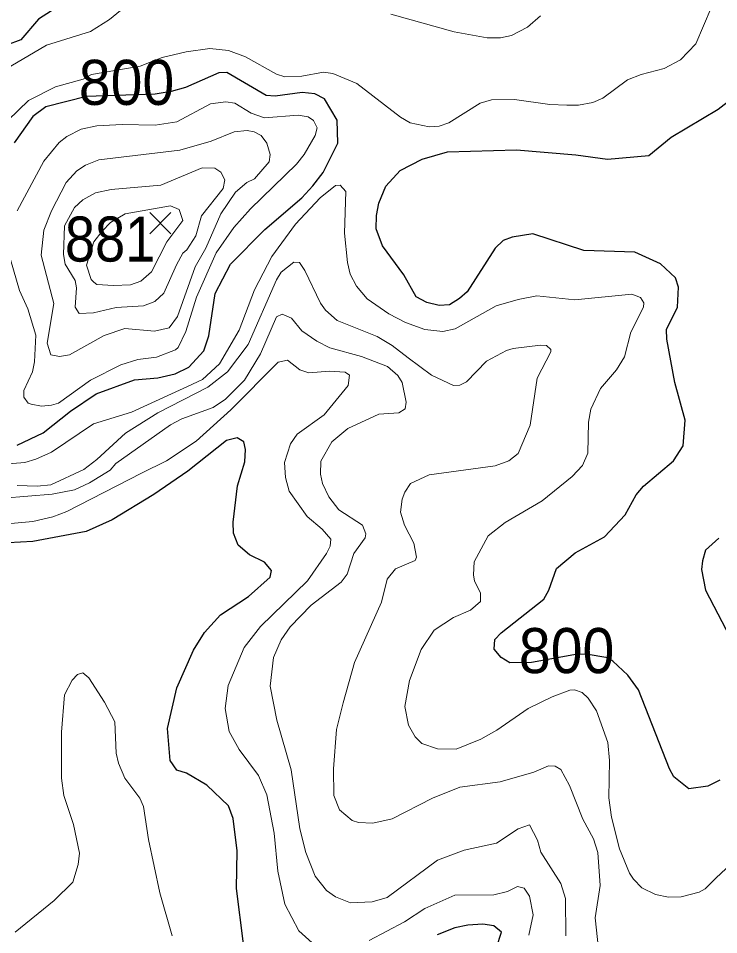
# Model space of a CAD drawing. Extents: x 294.2 to 320.3, y 7482.7 to 7510.7.
# Drawn here: x 312.401 to 313.645, y 7489.244 to 7490.87 of the extents above; entities that cross this region are included whole.
import ezdxf
from ezdxf.enums import TextEntityAlignment as Align

# ---------------------------------------------------------------- set-up
doc = ezdxf.new("R2010")
doc.units = 0
doc.header["$LTSCALE"] = 0.032
for name, color, linetype, lineweight in [('1', 7, 'Continuous', 25), ('2', 7, 'Continuous', 13), ('21', 7, 'Continuous', 25)]:
    doc.layers.add(name, color=color, linetype=linetype, lineweight=lineweight)
doc.layers.add('61', color=7, linetype='Continuous')

msp = doc.modelspace()

# ---------------------------------------------------------------- linework, layer by layer
at = {"layer": '1'}
for points in [[(312.942, 7490.9409), (312.9265, 7490.9269), (312.9165, 7490.9226), (312.8971, 7490.9269), (312.8622, 7490.9576), (312.8461, 7490.9645), (312.7994, 7490.9791), (312.7434, 7490.9904), (312.724, 7491.0038), (312.6774, 7491.056), (312.6652, 7491.0598), (312.6563, 7491.0565), (312.6463, 7491.0506), (312.6208, 7491.0156), (312.5992, 7490.964), (312.5693, 7490.9215), (312.5576, 7490.9113), (312.5232, 7490.8962), (312.5016, 7490.8898), (312.4595, 7490.8839), (312.4367, 7490.8688), (312.4051, 7490.8322), (312.3535, 7490.8134)], [(312.3988, 7490.1129), (312.445, 7490.1346), (312.4934, 7490.1734), (312.5392, 7490.2037), (312.6073, 7490.2285), (312.6484, 7490.2324), (312.6794, 7490.2394), (312.7035, 7490.251), (312.7306, 7490.28), (312.7395, 7490.3068), (312.7503, 7490.3822), (312.7779, 7490.4338), (312.8387, 7490.4959), (312.9046, 7490.5517), (312.924, 7490.5734), (312.9425, 7490.5967), (312.9681, 7490.6487), (312.9673, 7490.6898), (312.9444, 7490.7278), (312.9274, 7490.7363), (312.9049, 7490.7386), (312.8568, 7490.7324), (312.8413, 7490.7332), (312.771, 7490.7743), (312.757, 7490.7735), (312.6979, 7490.7479), (312.6724, 7490.7405), (312.6437, 7490.7358), (312.5222, 7490.7319), (312.4499, 7490.7132), (312.4266, 7490.6962), (312.3935, 7490.6497)], [(313.6468, 7489.5183), (313.6257, 7489.5074), (313.5918, 7489.5029), (313.565, 7489.524), (313.5574, 7489.5381), (313.5025, 7489.6785), (313.4833, 7489.7047), (313.4567, 7489.7295), (313.4477, 7489.7354), (313.4095, 7489.7418), (313.3878, 7489.7407), (313.3124, 7489.7273), (313.2741, 7489.7263), (313.2586, 7489.736), (313.2458, 7489.7505), (313.2475, 7489.7677), (313.2586, 7489.78), (313.334, 7489.8392), (313.3429, 7489.8553), (313.3568, 7489.8941), (313.39, 7489.9215), (313.4422, 7489.95), (313.4788, 7489.9889), (313.498, 7490.0246), (313.5114, 7490.0399), (313.5648, 7490.085), (313.582, 7490.1114), (313.5854, 7490.1571), (313.567, 7490.2243), (313.5526, 7490.3007), (313.5521, 7490.3184), (313.5715, 7490.3577), (313.5737, 7490.3932), (313.5682, 7490.4099), (313.5415, 7490.4346), (313.4961, 7490.4551), (313.4051, 7490.4583), (313.3147, 7490.4879), (313.2781, 7490.482), (313.262, 7490.4761), (313.2476, 7490.4626), (313.1983, 7490.3847), (313.1844, 7490.3734), (313.1667, 7490.3621), (313.1484, 7490.3605), (313.1262, 7490.3659), (313.1073, 7490.3761), (313.0857, 7490.4154), (313.0475, 7490.4664), (313.0364, 7490.4966), (313.0369, 7490.5202), (313.0414, 7490.5423), (313.0536, 7490.5724), (313.0791, 7490.6004), (313.1179, 7490.6203), (313.1634, 7490.6337), (313.2855, 7490.637), (313.3914, 7490.6284), (313.4474, 7490.6203), (313.5206, 7490.6268), (313.5605, 7490.6596), (313.6437, 7490.7091), (313.6914, 7490.7457)], [(312.8008, 7489.2278), (312.7881, 7489.3261), (312.7893, 7489.3925), (312.7823, 7489.45), (312.774, 7489.4729), (312.7357, 7489.5093), (312.6994, 7489.5304), (312.6821, 7489.5359), (312.6703, 7489.5532), (312.666, 7489.6098), (312.6825, 7489.6822), (312.7118, 7489.749), (312.7315, 7489.7804), (312.7598, 7489.8119), (312.8097, 7489.8441), (312.8483, 7489.8787), (312.8506, 7489.8905), (312.838, 7489.9054), (312.8113, 7489.918), (312.7916, 7489.9353), (312.783, 7489.9565), (312.7826, 7489.9762), (312.7904, 7490.0407), (312.803, 7490.0832), (312.8046, 7490.1052), (312.8015, 7490.1185), (312.7897, 7490.1256), (312.7704, 7490.1209), (312.702, 7490.0667), (312.6417, 7490.025), (312.5677, 7489.9801), (312.5216, 7489.9597), (312.4266, 7489.9416), (312.3383, 7489.9374)], [(313.6454, 7489.9476), (313.6216, 7489.9267), (313.6161, 7489.9073), (313.6144, 7489.8923), (313.6216, 7489.8557), (313.6723, 7489.7577)], [(313.2501, 7489.2212), (313.2588, 7489.2487), (313.2454, 7489.2598), (313.226, 7489.2629), (313.1992, 7489.261), (313.1762, 7489.2559), (313.1449, 7489.2437)]]:
    msp.add_lwpolyline(points, dxfattribs=at)
at = {"layer": '2'}
for points in [[(312.612, 7490.9089), (312.5626, 7490.8682), (312.5293, 7490.8471), (312.4507, 7490.8228), (312.3877, 7490.7857)], [(312.3826, 7490.6899), (312.4189, 7490.7245), (312.4666, 7490.749), (312.5159, 7490.7626), (312.5308, 7490.771), (312.6175, 7490.7857), (312.6565, 7490.801), (312.6987, 7490.8112), (312.7408, 7490.817), (312.774, 7490.8131), (312.8046, 7490.8023), (312.8596, 7490.7716), (312.8742, 7490.7665), (312.9046, 7490.7678), (312.9426, 7490.7748), (312.9592, 7490.7723), (313.0019, 7490.755), (313.0798, 7490.695), (313.0971, 7490.6848), (313.1303, 7490.6778), (313.1481, 7490.679), (313.1654, 7490.6848), (313.2209, 7490.7199), (313.2414, 7490.7256), (313.2822, 7490.7263), (313.3448, 7490.7174), (313.3754, 7490.7161), (313.3959, 7490.7161), (313.4214, 7490.7212), (313.4393, 7490.7288), (313.4827, 7490.7614), (313.507, 7490.771), (313.5478, 7490.7812), (313.5772, 7490.7965), (313.604, 7490.8253), (313.6315, 7490.8891)], [(313.3281, 7490.8751), (313.3052, 7490.8546), (313.2771, 7490.8399), (313.2573, 7490.8361), (313.2337, 7490.8361), (313.175, 7490.8463), (313.0626, 7490.8776)], [(312.387, 7490.4422), (312.403, 7490.3873), (312.4177, 7490.3547), (312.4317, 7490.3081), (312.4298, 7490.2608), (312.426, 7490.243), (312.4107, 7490.2098), (312.4107, 7490.1983), (312.4183, 7490.1874), (312.4235, 7490.1855), (312.442, 7490.1823), (312.4599, 7490.1836), (312.472, 7490.1874), (312.5288, 7490.2283), (312.5831, 7490.2557), (312.6131, 7490.2646), (312.6463, 7490.2691), (312.6801, 7490.2819), (312.6846, 7490.2864), (312.6986, 7490.3145), (312.7172, 7490.3758), (312.7522, 7490.4543), (312.7836, 7490.499), (312.8135, 7490.5322), (312.8947, 7490.6114), (312.9087, 7490.6286), (312.9278, 7490.6624), (312.9317, 7490.6759), (312.9253, 7490.6893), (312.9157, 7490.6956), (312.8979, 7490.6988), (312.8378, 7490.6937), (312.8142, 7490.702), (312.7855, 7490.7199), (312.7695, 7490.7225), (312.7421, 7490.7186), (312.6821, 7490.6866), (312.6437, 7490.6809), (312.585, 7490.6822), (312.5403, 7490.6796), (312.5122, 7490.6739), (312.4867, 7490.6605), (312.4732, 7490.6503), (312.4464, 7490.6171), (312.3985, 7490.529)], [(313.1231, 7490.3182), (313.0886, 7490.3305), (313.0587, 7490.3458), (313.0204, 7490.3725), (313.0013, 7490.3949), (312.9904, 7490.4166), (312.9853, 7490.4371), (312.9802, 7490.4894), (312.9828, 7490.5628), (312.9725, 7490.5743), (312.9643, 7490.5737), (312.9368, 7490.5519), (312.8932, 7490.505), (312.8513, 7490.4476), (312.8206, 7490.3885), (312.7931, 7490.317), (312.758, 7490.257), (312.728, 7490.2295), (312.7012, 7490.2168), (312.6016, 7490.1714), (312.5346, 7490.1504), (312.4599, 7490.1006), (312.4318, 7490.0878), (312.4126, 7490.082), (312.3756, 7490.0789)], [(312.3986, 7490.0412), (312.4343, 7490.0399), (312.4586, 7490.0424), (312.5173, 7490.0699), (312.5403, 7490.0872), (312.5914, 7490.1344), (312.6489, 7490.1702), (312.7376, 7490.2155), (312.7721, 7490.2429), (312.8091, 7490.2915), (312.8595, 7490.4064), (312.8678, 7490.4198), (312.8902, 7490.4377), (312.9004, 7490.437), (312.91, 7490.423), (312.9374, 7490.3649), (312.9464, 7490.3527), (312.9674, 7490.3343), (313.0383, 7490.3055), (313.0651, 7490.2896), (313.0932, 7490.2679), (313.1347, 7490.2372), (313.1737, 7490.2187), (313.1852, 7490.2193), (313.1967, 7490.2251), (313.2324, 7490.2621), (313.2682, 7490.2806), (313.2797, 7490.2845), (313.3282, 7490.2902), (313.339, 7490.2896), (313.3467, 7490.2826), (313.3467, 7490.2787), (313.3224, 7490.2315), (313.3097, 7490.1485), (313.2886, 7490.098)], [(313.6583, 7489.3612), (313.6397, 7489.344), (313.6206, 7489.3255), (313.6104, 7489.3197), (313.5785, 7489.3114), (313.5555, 7489.3108), (313.5325, 7489.3153), (313.5082, 7489.3274), (313.4936, 7489.3427), (313.4865, 7489.3529), (313.4686, 7489.3964), (313.4546, 7489.4525), (313.4495, 7489.487), (313.4507, 7489.5534), (313.4482, 7489.5853), (313.4277, 7489.6415), (313.4131, 7489.6639), (313.4023, 7489.6741), (313.3888, 7489.6785), (313.3805, 7489.6779), (313.3492, 7489.6664), (313.3065, 7489.6453), (313.2509, 7489.607), (313.2222, 7489.5911), (313.1788, 7489.5732), (313.1456, 7489.5738), (313.1174, 7489.5834), (313.106, 7489.5949), (313.0939, 7489.616), (313.0875, 7489.6492), (313.0958, 7489.6952), (313.1162, 7489.7501), (313.1392, 7489.7845), (313.1737, 7489.8069), (313.2043, 7489.8197), (313.2216, 7489.8356), (313.2216, 7489.8509), (313.2113, 7489.8714), (313.2094, 7489.8829), (313.2107, 7489.9059), (313.2356, 7489.9518), (313.2656, 7489.9754), (313.3313, 7490.0138), (313.3843, 7490.0572), (313.4029, 7490.0769), (313.4124, 7490.0987), (313.4137, 7490.1536), (313.4175, 7490.1766), (313.4348, 7490.2136), (313.4635, 7490.2468), (313.4775, 7490.2698), (313.489, 7490.3132), (313.5114, 7490.3579), (313.512, 7490.3655), (313.5057, 7490.3751), (313.4904, 7490.3808), (313.3895, 7490.3706)], [(313.3895, 7490.3706), (313.3218, 7490.3778), (313.2885, 7490.3714), (313.2494, 7490.3602), (313.1765, 7490.3193), (313.1547, 7490.3143), (313.1231, 7490.3182)], [(313.3735, 7489.2418), (313.3728, 7489.3082), (313.3646, 7489.3351), (313.3288, 7489.3906), (313.323, 7489.4117), (313.309, 7489.4391), (313.2886, 7489.4321), (313.2503, 7489.4065), (313.1928, 7489.3938), (313.1451, 7489.3763), (313.0562, 7489.3102), (313.0294, 7489.3025), (312.9911, 7489.3005), (312.9643, 7489.3114), (312.9483, 7489.3223), (312.9279, 7489.3478), (312.9113, 7489.39), (312.901, 7489.4321), (312.8857, 7489.5368), (312.8602, 7489.6249), (312.848, 7489.6849), (312.8538, 7489.736), (312.8678, 7489.7673), (312.8838, 7489.7903), (312.9208, 7489.8286), (312.9744, 7489.8694), (312.9847, 7489.8841), (312.9968, 7489.9205), (313.0172, 7489.9486), (313.0178, 7489.9557), (313.0121, 7489.971), (312.97, 7489.9978), (312.9521, 7490.0214), (312.9412, 7490.045), (312.9374, 7490.0616), (312.9381, 7490.0846), (312.9579, 7490.1185), (312.9859, 7490.1427), (313.0409, 7490.1676), (313.0766, 7490.1701), (313.0881, 7490.1772), (313.09, 7490.1893), (313.0824, 7490.2238), (313.0747, 7490.2366), (313.0568, 7490.2525), (313.0102, 7490.2704), (312.954, 7490.2857), (312.9311, 7490.2972), (312.9043, 7490.3155), (312.8859, 7490.3383), (312.8693, 7490.3455), (312.8595, 7490.3405), (312.8308, 7490.2749), (312.8027, 7490.2282), (312.7689, 7490.1944), (312.7472, 7490.1798), (312.691, 7490.1593), (312.6712, 7490.1491), (312.5741, 7490.0801), (312.5639, 7490.0686), (312.5275, 7490.0457), (312.5007, 7490.0335), (312.4611, 7490.0258), (312.3743, 7490.0189)], [(312.9285, 7489.2239), (312.8991, 7489.2508), (312.8742, 7489.298), (312.8615, 7489.3568), (312.8551, 7489.4244), (312.8423, 7489.4921), (312.8276, 7489.5266), (312.7931, 7489.5725), (312.7752, 7489.6045), (312.7682, 7489.6454), (312.7733, 7489.6862), (312.8021, 7489.7539), (312.8308, 7489.7909), (312.9144, 7489.872), (312.9483, 7489.9205), (312.9547, 7489.9333), (312.956, 7489.946), (312.9406, 7489.9639), (312.9138, 7489.9863), (312.8819, 7490.031), (312.8755, 7490.0553), (312.8736, 7490.0821), (312.8844, 7490.1153), (312.8959, 7490.1325), (312.9442, 7490.1668), (312.9867, 7490.2186), (312.9889, 7490.2372), (312.9815, 7490.2422), (312.9534, 7490.2439), (312.9166, 7490.2411), (312.9011, 7490.2467), (312.8788, 7490.2637), (312.8621, 7490.2603), (312.7784, 7490.1753), (312.7165, 7490.1197), (312.6642, 7490.0853), (312.6195, 7490.0629), (312.4867, 7489.9952), (312.4624, 7489.9857), (312.4267, 7489.9773), (312.3475, 7489.9703)], [(313.2886, 7490.098), (313.272, 7490.0853), (313.2477, 7490.0763), (313.1303, 7490.0603), (313.0977, 7490.045), (313.0875, 7490.0297), (313.0824, 7490.017)], [(313.0824, 7490.017), (313.0798, 7489.994), (313.0868, 7489.971), (313.1034, 7489.939), (313.1079, 7489.9141), (313.106, 7489.9084), (313.0709, 7489.8931), (313.0562, 7489.8752), (313.0459, 7489.8343), (312.9981, 7489.7271), (312.9777, 7489.6556), (312.9662, 7489.6083), (312.9604, 7489.5381), (312.9611, 7489.4908), (312.9713, 7489.4653), (312.9936, 7489.4468), (313.0051, 7489.443), (313.0307, 7489.4417), (313.0651, 7489.4493), (313.1366, 7489.4864), (313.1852, 7489.5055), (313.2567, 7489.5151), (313.3167, 7489.5323), (313.3428, 7489.5438), (313.3544, 7489.5432), (313.3646, 7489.5374), (313.3799, 7489.5087), (313.4035, 7489.4487), (313.4226, 7489.4142), (313.4303, 7489.39), (313.4341, 7489.3312), (313.4252, 7489.2738), (313.4329, 7489.2023)], [(312.4962, 7489.6958), (312.5058, 7489.706), (312.5154, 7489.7086), (312.5262, 7489.6996), (312.5537, 7489.6569), (312.5722, 7489.6217), (312.5747, 7489.5662), (312.5786, 7489.5483), (312.5901, 7489.5215), (312.6169, 7489.4864), (312.6233, 7489.4717), (312.6322, 7489.413), (312.652, 7489.3185), (312.6743, 7489.2418)], [(312.5096, 7489.3887), (312.4988, 7489.4398), (312.4815, 7489.4908), (312.4777, 7489.5215), (312.4777, 7489.6032), (312.4828, 7489.6696), (312.4962, 7489.6958)], [(312.3954, 7489.2482), (312.4643, 7489.3044), (312.4975, 7489.337), (312.5071, 7489.3683), (312.5096, 7489.3887)], [(313.3077, 7489.2431), (313.3154, 7489.2789), (313.309, 7489.3121), (313.2995, 7489.3267), (313.2873, 7489.3293), (313.2695, 7489.3204), (313.2452, 7489.3146), (313.1762, 7489.314), (313.1226, 7489.2903), (313.0868, 7489.2667), (313.0243, 7489.2335)]]:
    msp.add_lwpolyline(points, dxfattribs=at)
for points in [[(312.7433, 7490.6522), (312.6878, 7490.6362), (312.5441, 7490.619), (312.5199, 7490.6101), (312.5045, 7490.5999), (312.486, 7490.5788), (312.4598, 7490.529), (312.4464, 7490.4945), (312.4413, 7490.4498), (312.4636, 7490.3643), (312.4522, 7490.2941), (312.4585, 7490.273), (312.4739, 7490.2704), (312.4918, 7490.273), (312.5531, 7490.3075), (312.5901, 7490.3202), (312.6425, 7490.3151), (312.6686, 7490.3208), (312.6833, 7490.3413), (312.7152, 7490.4294), (312.7338, 7490.4626), (312.7606, 7490.5233), (312.7867, 7490.5616), (312.8065, 7490.5788), (312.8206, 7490.5858), (312.8461, 7490.6158), (312.848, 7490.6286), (312.8423, 7490.649), (312.8321, 7490.6624), (312.82, 7490.6688), (312.8072, 7490.6714), (312.7842, 7490.6688)], [(312.7605, 7490.5972), (312.7497, 7490.6043), (312.7274, 7490.605), (312.654, 7490.5743), (312.5659, 7490.5667), (312.5377, 7490.5609), (312.5154, 7490.5481), (312.5007, 7490.5347), (312.4827, 7490.5022), (312.481, 7490.4511), (312.4843, 7490.4339), (312.5015, 7490.4049), (312.5039, 7490.3923), (312.502, 7490.3579), (312.509, 7490.3464), (312.5346, 7490.3476), (312.5748, 7490.3573), (312.6233, 7490.3604), (312.6431, 7490.3681), (312.659, 7490.3828), (312.682, 7490.4332), (312.6929, 7490.4536), (312.6999, 7490.4594), (312.7159, 7490.4843), (312.7261, 7490.5201), (312.7644, 7490.5686), (312.7676, 7490.5839)], [(312.5697, 7490.3962), (312.5403, 7490.3981), (312.5352, 7490.4019), (312.5301, 7490.407), (312.5218, 7490.4326), (312.5352, 7490.4735), (312.5496, 7490.4924), (312.5646, 7490.508), (312.5907, 7490.5233), (312.6711, 7490.5376), (312.6866, 7490.5311), (312.6928, 7490.5117), (312.6645, 7490.4737), (312.6373, 7490.4205), (312.6182, 7490.4038), (312.6003, 7490.3975)]]:
    msp.add_lwpolyline(points, close=True, dxfattribs=at)
at = {"layer": '21'}
for p, q in [((312.6342, 7490.5257), (312.6717, 7490.4882)), ((312.6717, 7490.5257), (312.6342, 7490.4882))]:
    msp.add_line(p, q, dxfattribs=at)

# ---------------------------------------------------------------- texts
at = {"layer": '61'}
for s, width, p in [('800', 0.95, (312.593, 7490.7168)), ('881', 0.9, (312.5639, 7490.4387)), ('800', 0.95, (313.3747, 7489.7082))]:
    msp.add_text(s, height=0.08, dxfattribs=dict(at, width=width)).set_placement(p, align=Align.CENTER)

doc.saveas('drawing.dxf')
